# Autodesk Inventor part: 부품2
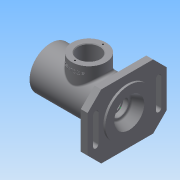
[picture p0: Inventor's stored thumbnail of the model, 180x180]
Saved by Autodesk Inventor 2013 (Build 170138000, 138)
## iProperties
Created: 2017-10
Part Number: 부품2
Material: 일반
Document SubType Name: Modeling
Designer: Windows7
Density: 1 g/cm^3
Author: Windows7
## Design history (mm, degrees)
sketch "스케치1"
  geometry: L1 (-57.5, 0)-(57.5, 0); L2 (-57.5, 21)-(-57.5, 31); L3 (-57.5, 31)-(57.5, 31); L4 (57.5, 31)-(57.5, 16); L5 (36.2, 12.5)-(36.2, 10); L6 (36.2, 10)-(33.5, 10); L7 (33.5, 10)-(33.5, 16.5); L8 (33.5, 16.5)-(28.5, 16.5); L9 (28.5, 16.5)-(28.5, 17.5); L10 (28.5, 17.5)-(17.5, 17.5); L11 (17.5, 17.5)-(17.5, 26); L12 (17.5, 26)-(-20.5, 26); L13 (-20.5, 26)-(-20.5, 17.5); L14 (-20.5, 17.5)-(-31.5, 17.5); L15 (-31.5, 17.5)-(-31.5, 18.5); L16 (-31.5, 18.5)-(-33.25, 18.5); L17 (-33.25, 18.5)-(-33.25, 17.5); L18 (-33.25, 17.5)-(-36.5, 17.5); L19 (-36.5, 17.5)-(-36.5, 20); L20 (-36.5, 20)-(-45.5, 20); L21 (-45.5, 20)-(-45.5, 24); L22 (-45.5, 24)-(-48.5, 24); L23 (-48.5, 24)-(-48.5, 21); L24 (-48.5, 21)-(-57.5, 21); L25 (36.2, 12.5)-(43.5, 12.5); L26 (43.5, 12.5)-(43.5, 16); L27 (43.5, 16)-(57.5, 16); L28 (17.5, -26)-(-20.5, -26); 2 further points
  constraints: 56 end point, 21 parallel, 4 perpendicular, 2 symmetric about line, 2 vertical alignment, 1 coincident, 1 horizontal, 1 midpoint, 1 vertical
  dimensions: "d0" = 115 distance of L1.start L1.end; "d2" = 42 diameter of L24 L1; "d3" = 48 diameter of L22 L1; "d4" = 40 diameter of L20 L1; "d5" = 35 diameter of L18 L1; "d6" = 37 diameter of L16 L1; "d7" = 35 diameter of L14 L1; "d9" = 35 diameter of L10 L1; "d10" = 33 diameter of L8 L1; "d11" = 20 diameter of L6 L1; "d14" = 12 distance between parallel lines of L2 L21; "d15" = 3 distance between parallel lines of L21 L23; "d16" = 21 distance between parallel lines of L2 L19; "d18" = 38 distance between parallel lines of L11 L13; "d22" = 11 distance between parallel lines of L15 L13; "d25" = 11 distance between parallel lines of L11 L9; "d26" = 5 distance between parallel lines of L9 L7; "d31" = 62 diameter of L3 L1; "d32" = 2.7 distance between parallel lines of L7 L5; "d34" = 25 diameter of L25 L1; "d35" = 7.3 distance between parallel lines of L5 L26; "d36" = 32 diameter of L27 L1; "d118" = 26 distance between parallel lines of L2 L15; "d119" = 1.75 distance between parallel lines of L15 L17; "d122" = 52 distance between parallel lines of L12 L28
revolve "회전1" sketch "스케치1" stored, may be unused: angle "d37" = 90 deg
node "작업 평면1"
sketch "스케치2"
  geometry: 1 further point
sketch "스케치3"
  geometry: L1 (-58, 47)-(58, 47); L2 (58, 47)-(58, -47); L3 (58, -47)-(-58, -47); L4 (-58, -47)-(-58, 47); L5 (-58, 47)-(58, -47); C1 r 31 at (0, 0) reference; C2 r 16 at (0, 0) reference; 2 further points
  constraints: 10 end point, 2 parallel, 1 coincident, 1 horizontal, 1 midpoint, 1 perpendicular
  dimensions: "d43" = 116 distance between parallel lines of L2 L4; "d45" = 94 distance between parallel lines of L3 L1
extrude "돌출1" join sketch "스케치3" distance "d46" = 10; taper "d47" = 0 deg
chamfer "모따기1" distance "d48" = 20; stored, may be unused: second distance "d49" = 2, angle "d50" = 45 deg
sketch "스케치4"
  geometry: L1 (-38, -47)-(38, -47) reference; L2 (-50, 20)-(-50, -20); L3 (-42, -20)-(-42, 20); C1 r 31 at (0, 0) reference; A1 r 4 centre (-46, -20) between (-50, -20) and (-42, -20); A2 r 4 centre (-46, 20) between (-42, 20) and (-50, 20)
  constraints: 4 end point, 4 point on circle, 4 tangent, 2 centre point, 1 parallel, 1 perpendicular
  dimensions: "d51" = 46 horizontal distance of C1.centre A1.centre; "d52" = 40 distance of A2.centre A1.centre; "d53" = 20 vertical distance of A1.centre C1.centre; "d55" = 4 radius of A2
extrude "돌출2" cut sketch "스케치4" stored distance "d56" = 10; taper "d57" = 0 deg
sketch "스케치5"
  geometry: C1 r 31 at (0, 0) reference; C2 r 35 at (0, 0)
  constraints: 1 centre point, 1 coincident
  dimensions: "d58" = 70 diameter of C2
extrude "돌출3" join sketch "스케치5" distance "d60" = 3; taper "d61" = 0 deg
node "작업 평면2"
sketch "스케치6"
  geometry: L1 (57.5, 31)-(57.5, -31) reference; C1 r 25 at (1.5, 0); 2 further points
  constraints: 1 centre point, 1 coincident, 1 horizontal alignment, 1 midpoint
  dimensions: "d63" = 50 diameter of C1; "d121" = 31 distance edge to line of C1 L1
extrude "돌출4" join sketch "스케치6" stored distance "d65" = 3; taper "d66" = 0 deg
sketch "스케치7"
  geometry: C1 r 25 at (0, 0) reference
hole "구멍1" sketch "스케치7" at (0, 0) diameter "d67" = 32; stored, may be unused: countersink angle "d71" = 90 deg, drill point angle "d73" = 0 deg; dims "d68" = 6, "d69" = 32, "d70" = 2, "d72" = 8
chamfer "모따기2" distance "d74" = 1; stored, may be unused: second distance "d75" = 2, angle "d76" = 45 deg
feature "스레드1" dims "d77" = 10, "d78" = 0
chamfer "모따기3" distance "d79" = 1; stored, may be unused: second distance "d80" = 2, angle "d81" = 45 deg
chamfer "모따기4" distance "d82" = 1; stored, may be unused: second distance "d83" = 2, angle "d84" = 45 deg
chamfer "모따기5" distance "d85" = 1; stored, may be unused: second distance "d86" = 2, angle "d87" = 45 deg
chamfer "모따기6" distance "d88" = 0.7; stored, may be unused: second distance "d89" = 2, angle "d90" = 30 deg
fillet "모깎기1" dims "d91" = 0.3
fillet "모깎기2" dims "d92" = 0.3
fillet "모깎기3" dims "d93" = 3
fillet "모깎기4" dims "d94" = 3
sketch "스케치8"
  geometry: L1 (-18.5, 47)-(-17.5, 46) reference; L2 (-17.5, 46)-(-17.5, 26) reference; L3 (-20.5, 23)-(-20.5, 18.5) reference; L4 (-20.5, 18.5)-(-21.5, 17.5) reference; L5 (-21.5, 17.5)-(-31.5, 17.5) reference; L6 (-31.5, 17.5)-(-31.5, 18.5) reference; L7 (-31.5, 18.5)-(-33.25, 18.5) reference; L8 (-33.25, 18.5)-(-33.25, 17.5) reference; L9 (-33.25, 17.5)-(-36.5, 17.5) reference; L10 (-36.5, 17.5)-(-36.5, 20) reference; L11 (-36.5, 20)-(-45.5, 20) reference; L12 (-45.5, 20)-(-45.5, 24) reference; L13 (-45.5, 24)-(-48.5, 24) reference; L14 (-48.5, 24)-(-48.5, 21) reference; L15 (-48.5, 21)-(-56.5, 21) reference; L16 (-56.5, 21)-(-57.5, 22) reference; L17 (-57.5, 22)-(-57.5, 31) reference; L18 (-57.5, 31)-(-26.5, 31) reference; L19 (-26.5, 31)-(-26.5, 47) reference; L20 (-26.5, 47)-(-18.5, 47) reference; L21 (57.5, -35)-(54.5, -35) reference; L22 (54.5, -35)-(54.5, -47) reference; L23 (54.5, -47)-(44.5, -47) reference; L24 (44.5, -47)-(44.5, -31) reference; L25 (44.5, -31)-(-57.5, -31) reference; L26 (-57.5, -31)-(-57.5, -22) reference; L27 (-57.5, -22)-(-56.5, -21) reference; L28 (-56.5, -21)-(-48.5, -21) reference; L29 (-48.5, -21)-(-48.5, -24) reference; L30 (-48.5, -24)-(-45.5, -24) reference; L31 (-45.5, -24)-(-45.5, -20) reference; L32 (-45.5, -20)-(-36.5, -20) reference; L33 (-36.5, -20)-(-36.5, -17.5) reference; L34 (-36.5, -17.5)-(-33.25, -17.5) reference; L35 (-33.25, -17.5)-(-33.25, -18.5) reference; L36 (-33.25, -18.5)-(-31.5, -18.5) reference; L37 (-31.5, -18.5)-(-31.5, -17.5) reference; L38 (-31.5, -17.5)-(-21.5, -17.5) reference; L39 (-21.5, -17.5)-(-20.5, -18.5) reference; L40 (-20.5, -18.5)-(-20.5, -23) reference; L41 (-17.5, -26)-(14.5, -26) reference; L42 (17.5, -23)-(17.5, -18.5) reference; L43 (17.5, -18.5)-(18.5, -17.5) reference; L44 (18.5, -17.5)-(28.2, -17.5) reference; L45 (28.5, -17.2)-(28.5, -16.5) reference; L46 (28.5, -16.5)-(30.5, -16.5) reference; L47 (33.5, -13.5)-(33.5, -10) reference; L48 (33.5, -10)-(36.2, -10) reference; L49 (36.2, -10)-(36.2, -12.2) reference; L50 (36.5, -12.5)-(42.8, -12.5) reference; L51 (42.8, -12.5)-(43.5, -12.904) reference; L52 (43.5, -12.904)-(43.5, -16) reference; L53 (43.5, -16)-(57.5, -16) reference; L54 (57.5, -16)-(57.5, -35) reference; L55 (54.5, 35)-(57.5, 35) reference; L56 (57.5, 35)-(57.5, 16) reference; L57 (57.5, 16)-(43.5, 16) reference; L58 (43.5, 16)-(43.5, 12.904) reference; L59 (43.5, 12.904)-(42.8, 12.5) reference; L60 (42.8, 12.5)-(36.5, 12.5) reference; L61 (36.2, 12.2)-(36.2, 10) reference; L62 (36.2, 10)-(33.5, 10) reference; L63 (33.5, 10)-(33.5, 13.5) reference; L64 (30.5, 16.5)-(28.5, 16.5) reference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; A1 r 3 centre (-17.5, 23) between (-17.5, 26) and (-20.5, 23) reference; A2 r 3 centre (-17.5, -23) between (-20.5, -23) and (-17.5, -26) reference; A3 r 3 centre (14.5, -23) between (14.5, -26) and (17.5, -23) reference; A4 r 0.3 centre (28.2, -17.2) between (28.2, -17.5) and (28.5, -17.2) reference; A5 r 3 centre (30.5, -13.5) between (30.5, -16.5) and (33.5, -13.5) reference; A6 r 0.3 centre (36.5, -12.2) between (36.2, -12.2) and (36.5, -12.5) reference; A7 r 0.3 centre (36.5, 12.2) between (36.5, 12.5) and (36.2, 12.2) reference; A8 r 3 centre (30.5, 13.5) between (33.5, 13.5) and (30.5, 16.5) reference; A9 r 0.3 centre (28.2, 17.2) between (28.5, 17.2) and (28.2, 17.5) reference; A10 r 3 centre (14.5, 23) between (17.5, 23) and (14.5, 26) reference; 2 further points
  constraints: 4 end point, 1 horizontal alignment, 1 midpoint, 1 perpendicular, 1 point on line
  dimensions: "d95" = 44 diameter of L78.end L77
revolve "회전2" sketch "스케치8" stored, may be unused: angle "d97" = 90 deg
fillet "모깎기5" dims "d98" = 3
sketch "스케치9" dims "d99" = 41
  geometry: C1 r 25 at (0, 0) reference; C2 r 17 at (0, 0) reference; 2 further points
  constraints: 2 vertical alignment, 1 coincident, 2 other
hole "구멍2" sketch "스케치9" at (0, 20.5) diameter "d101" = 2.459; stored, may be unused: countersink angle "d105" = 90 deg, drill point angle "d107" = 118 deg; dims "d102" = 6, "d103" = 32, "d104" = 2, "d106" = 8
node "작업 평면3"
sketch "스케치10"
  geometry: L1 (-25, 0)-(25, 0) reference; L2 (-56, -78)-(-56, -16) reference; 2 further points
  constraints: 1 other
  dimensions: "d111" = 10 distance from line of L1 point (0, -10); "d112" = 56 distance from line of L2 point (0, -10)
feature "엠보싱1" sketch "스케치10" dims "d0" = 115, "d2" = 42, "d3" = 48, "d4" = 40, "d5" = 35, "d6" = 37, "d7" = 35, "d9" = 35, "d10" = 33, "d11" = 20, "d14" = 12, "d15" = 3, "d16" = 21, "d18" = 38, "d22" = 11, "d25" = 11, "d26" = 5, "d31" = 62, "d32" = 2.7, "d34" = 25, "d35" = 7.3, "d36" = 32, "d113" = 0.5, "d114" = 0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
fillet "모깎기6" dims "d115" = 3
fillet "모깎기7" dims "d116" = 3
node "솔리드1"
mirror "대칭1"
pattern_circular "원형 패턴1" dims angle "d109" = 360 deg
node "절단 모서리 투영1"
node "절단 모서리 투영2"
other parameters: "d38" = -13, "d39" = 0.5, "d40" = 2, "d41" = 0, "d62" = 47
